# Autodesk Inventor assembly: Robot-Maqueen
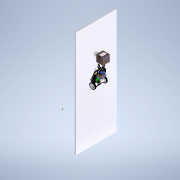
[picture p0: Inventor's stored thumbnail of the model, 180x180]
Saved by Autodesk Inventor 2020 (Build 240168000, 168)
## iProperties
Created: 2021-11
Part Number: Robot-Maqueen
Document SubType Name: Assembly
Designer: bruno
Author: bruno
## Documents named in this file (9)
- C:\Users\bruno\OneDrive\Bureau\Robot-Inventor\Robot-equillibrage\Robot-Maqueen.iam
- C:\Users\bruno\OneDrive\Bureau\Robot-Inventor\Robot-equillibrage\tapis.ipt
- C:\Users\bruno\OneDrive\Bureau\Robot-Inventor\Robot-equillibrage\Ensemble-base.iam
- C:\Users\bruno\OneDrive\Bureau\Robot-Inventor\Robot-equillibrage\Roulette.ipt
- C:\Users\bruno\OneDrive\Bureau\Robot-Inventor\Robot-equillibrage\roue.ipt
- C:\Users\bruno\OneDrive\Bureau\Robot-Inventor\Robot-equillibrage\Ensemble-pince.iam
- C:\Users\bruno\OneDrive\Bureau\Robot-Inventor\Robot-equillibrage\Ensemble-pince-2.iam
- C:\Users\bruno\OneDrive\Bureau\Robot-Inventor\Robot-equillibrage\support-colis.ipt
- C:\Users\bruno\OneDrive\Bureau\Robot-Inventor\Robot-equillibrage\colis.ipt
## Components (9 placed, 8 different names)
1. tapis:1 — Tangente:1, Tangente:2, Affleurement:1, Affleurement:2, Tangente:3, Placage:5
2. Ensemble-base:1 [sub-assembly] — Logement:2, Logement:3, Placage:1, Placage:2, Placage:3, Placage:4
3. Roulette:1 — Placage:1, Affleurement:2, Tangente:3
4. roue:1 — Logement:3, Tangente:2
5. roue:2 — Logement:2, Tangente:1, Affleurement:1
6. Ensemble-pince:1 [sub-assembly] — Placage:2, Affleurement:3, Rotation:1
7. Ensemble-pince-2:1 [sub-assembly] — Placage:3, Placage:4, Affleurement:3, Rotation:1
8. support-colis:1 — Placage:5, Placage:6
9. colis:1 — Placage:6
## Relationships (15: Mate 6, Tangent 3, Flush 3, Insert 2, RelateRotation 1)
- Logement:2 [Insert]: Ensemble-base:1 ↔ roue:2
- Logement:3 [Insert]: Ensemble-base:1 ↔ roue:1
- Tangente:1: tapis:1 ↔ roue:2
- Tangente:2: tapis:1 ↔ roue:1
- Affleurement:1 [Flush]: tapis:1 ↔ roue:2
- Placage:1 [Mate]: Ensemble-base:1 ↔ Roulette:1
- Affleurement:2 [Flush]: tapis:1 ↔ Roulette:1
- Tangente:3: tapis:1 ↔ Roulette:1
- Placage:2 [Mate]: Ensemble-base:1 ↔ Ensemble-pince:1
- Placage:3 [Mate]: Ensemble-base:1 ↔ Ensemble-pince-2:1
- Placage:4 [Mate]: Ensemble-base:1 ↔ Ensemble-pince-2:1
- Affleurement:3 [Flush]: Ensemble-pince:1 ↔ Ensemble-pince-2:1
- Rotation:1 [RelateRotation]: Ensemble-pince:1 ↔ Ensemble-pince-2:1
- Placage:5 [Mate]: tapis:1 ↔ support-colis:1
- Placage:6 [Mate]: support-colis:1 ↔ colis:1
